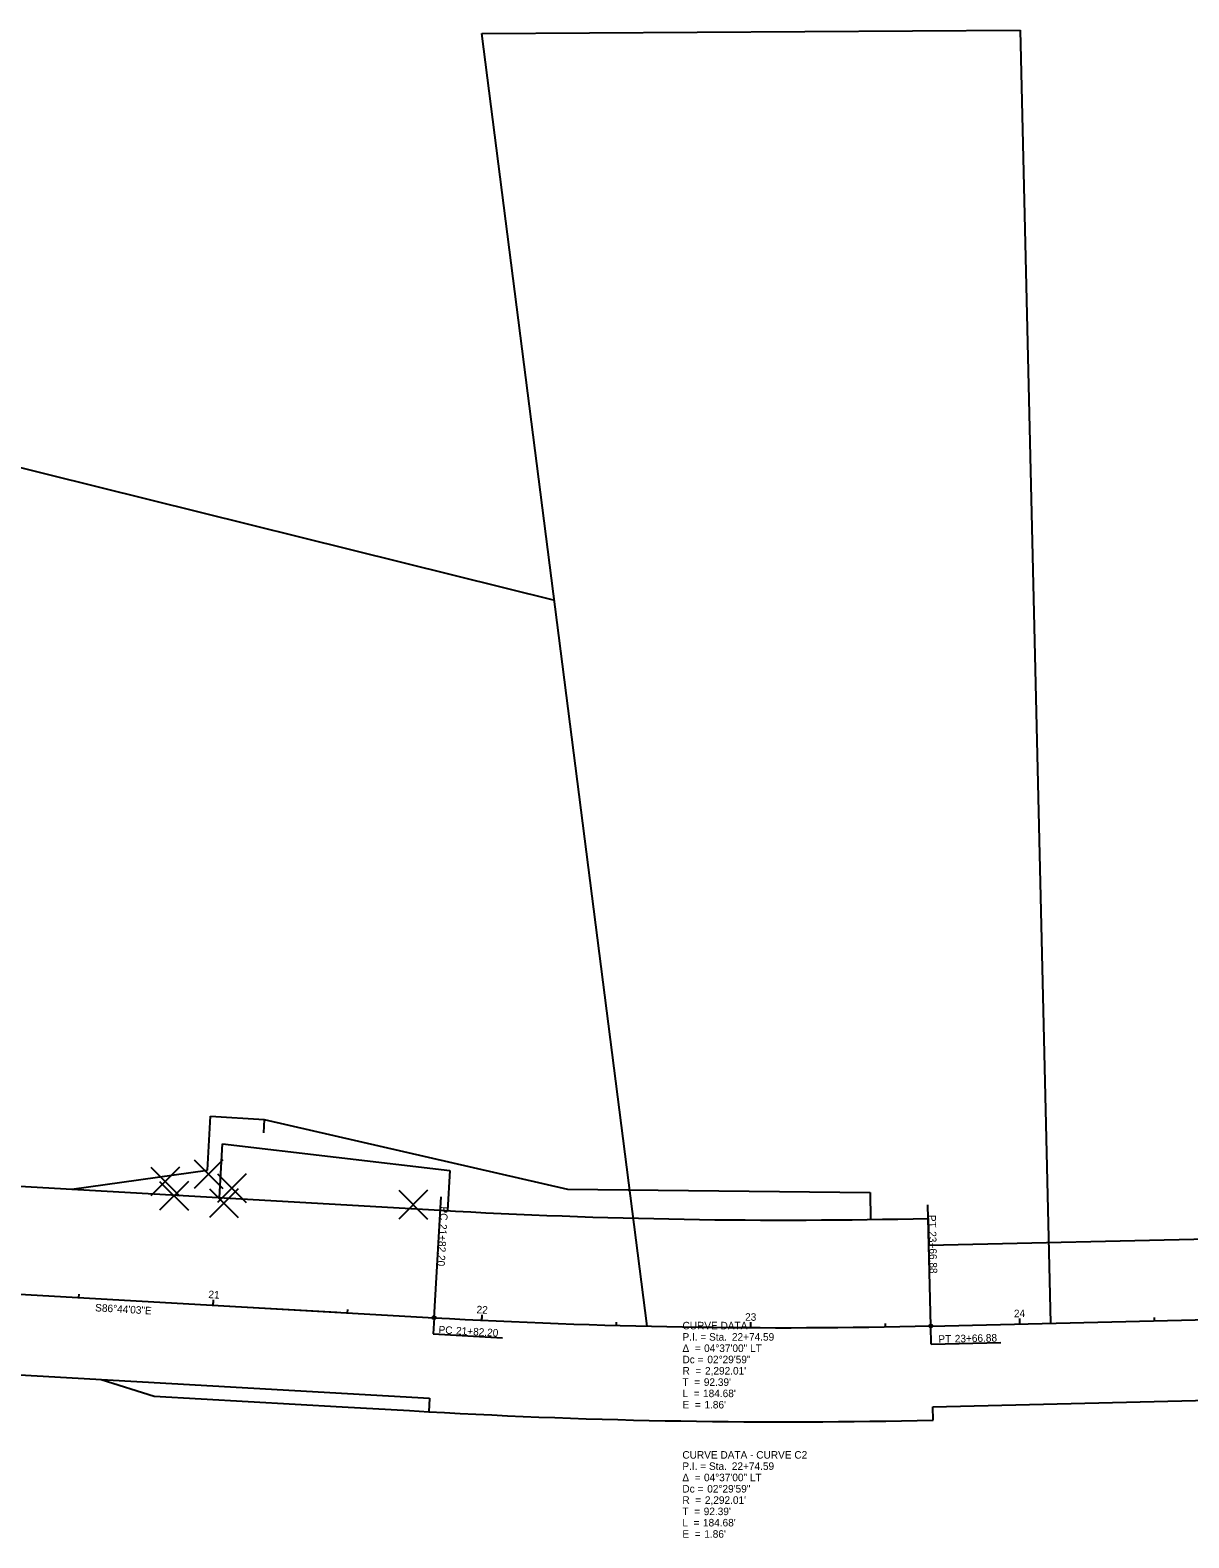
# Model space of a CAD drawing. Extents: x 2273856 to 2278684, y 652916 to 655179.
# Drawn here: x 2274537 to 2274968, y 654619 to 655179 of the extents above; entities that cross this region are included whole.
import ezdxf

# ---------------------------------------------------------------- set-up
doc = ezdxf.new("R2010")
doc.units = 0
for name, color, linetype in [('DV_X_Property_Line', 7, 'Continuous'), ('RW_P_Esmt_SH', 7, 'Continuous'), ('RW_P_Esmt_TMP', 7, 'Continuous'), ('RW_X_CL', 7, 'Continuous'), ('RW_X_CL_1000_Curve_Data', 7, 'Continuous'), ('RW_X_CL_1000_Stations', 7, 'Continuous'), ('RW_X_CL_100_Curve_Data', 7, 'Continuous'), ('RW_X_CL_100_Stations', 7, 'Continuous'), ('RW_X_CL_500_Curve_Data', 7, 'Continuous'), ('RW_X_CL_500_Stations', 7, 'Continuous'), ('RW_X_Esmt_SH', 7, 'Continuous'), ('SC_Scratch1', 7, 'Continuous'), ('VG_P_Cells', 7, 'Continuous')]:
    doc.layers.add(name, color=color, linetype=linetype)

msp = doc.modelspace()

# ---------------------------------------------------------------- linework, layer by layer
at = {"layer": 'DV_X_Property_Line'}
for p, q in [((2274705.29, 655177.83), (2274905.28, 655179.09)), ((2274766.64, 654697.37), (2274705.29, 655177.83)), ((2274905.28, 655179.09), (2274916.62, 654698.48)), ((2274486.83, 655028.17), (2274732.19, 654967.18))]:
    msp.add_line(p, q, dxfattribs=at)
at = {"layer": 'RW_P_Esmt_SH'}
for p, q in [((2274607.72, 654745.14), (2274608.86, 654765.1)), ((2274608.86, 654765.1), (2274693.37, 654755.28)), ((2274693.37, 654755.28), (2274692.53, 654740.3))]:
    msp.add_line(p, q, dxfattribs=at)
at = {"layer": 'RW_P_Esmt_TMP'}
for p, q in [((2274603.3, 654755.41), (2274604.43, 654775.37)), ((2274603.3, 654755.41), (2274604.43, 654775.37)), ((2274604.43, 654775.37), (2274624.4, 654774.23)), ((2274604.43, 654775.37), (2274624.4, 654774.23)), ((2274624.4, 654774.23), (2274624.12, 654769.24)), ((2274624.4, 654774.23), (2274737.06, 654748.26)), ((2274624.4, 654774.23), (2274737.06, 654748.26)), ((2274552.81, 654748.27), (2274603.3, 654755.41)), ((2274552.81, 654748.27), (2274603.3, 654755.41)), ((2274737.06, 654748.26), (2274849.53, 654747.02)), ((2274737.06, 654748.26), (2274849.53, 654747.02)), ((2274849.53, 654747.02), (2274849.67, 654737.02)), ((2274849.53, 654747.02), (2274849.67, 654737.02)), ((2274563.8, 654677.53), (2274583.48, 654671.4)), ((2274583.48, 654671.4), (2274653.36, 654667.41)), ((2274653.36, 654667.41), (2274678.32, 654665.99)), ((2274678.32, 654665.99), (2274685.51, 654665.58))]:
    msp.add_line(p, q, dxfattribs=at)
at = {"layer": 'RW_X_CL'}
for p, q in [((2274458.12, 654713.61), (2274687.5, 654700.52)), ((2274872.11, 654697.43), (2275371.97, 654709.22))]:
    msp.add_line(p, q, dxfattribs=at)
msp.add_arc((2274818.07, 656988.81), 2292.01, 266.73428, 271.35095, dxfattribs=at)
at = {"layer": 'RW_X_CL_1000_Stations'}
for p, q in [((2274687.5, 654700.52), (2274690.07, 654745.45)), ((2274872.11, 654697.43), (2274871.05, 654742.42))]:
    msp.add_line(p, q, dxfattribs=at)
for centre in [(2274687.5, 654700.52), (2274872.11, 654697.43)]:
    msp.add_circle(centre, 0.6, dxfattribs=at)
at = {"layer": 'RW_X_CL_100_Stations'}
for p, q in [((2274555.52, 654708.05), (2274555.59, 654709.25)), ((2274605.44, 654705.2), (2274605.55, 654707.2)), ((2274655.36, 654702.35), (2274655.43, 654703.55)), ((2274705.28, 654699.57), (2274705.38, 654701.57)), ((2274687.5, 654700.52), (2274687.16, 654694.53)), ((2274755.24, 654697.66), (2274755.28, 654698.86)), ((2274805.23, 654696.83), (2274805.25, 654698.83)), ((2274855.23, 654697.1), (2274855.21, 654698.3)), ((2274872.27, 654690.69), (2274872.11, 654697.43)), ((2274905.22, 654698.22), (2274905.17, 654700.21)), ((2274955.21, 654699.39), (2274955.18, 654700.59)), ((2274687.16, 654694.53), (2274712.88, 654693.07)), ((2274872.27, 654690.69), (2274898.15, 654691.3))]:
    msp.add_line(p, q, dxfattribs=at)
for centre in [(2274687.5, 654700.52), (2274872.11, 654697.43)]:
    msp.add_circle(centre, 0.6, dxfattribs=at)
at = {"layer": 'RW_X_CL_500_Stations'}
for p, q in [((2274687.5, 654700.52), (2274690.07, 654745.45)), ((2274872.11, 654697.43), (2274871.05, 654742.42)), ((2274605.44, 654705.2), (2274605.51, 654706.4)), ((2274705.28, 654699.57), (2274705.34, 654700.77)), ((2274805.23, 654696.83), (2274805.24, 654698.03)), ((2274905.22, 654698.22), (2274905.19, 654699.42))]:
    msp.add_line(p, q, dxfattribs=at)
for centre in [(2274687.5, 654700.52), (2274872.11, 654697.43)]:
    msp.add_circle(centre, 0.6, dxfattribs=at)
at = {"layer": 'RW_X_Esmt_SH'}
for p, q in [((2274460.4, 654753.54), (2274689.78, 654740.45)), ((2274871.17, 654737.42), (2274871.4, 654727.43)), ((2274871.4, 654727.43), (2275371.26, 654739.21)), ((2274456.41, 654683.66), (2274685.8, 654670.57)), ((2274872.82, 654667.44), (2275372.68, 654679.23)), ((2274685.8, 654670.57), (2274685.51, 654665.58)), ((2274872.94, 654662.44), (2274872.82, 654667.44))]:
    msp.add_line(p, q, dxfattribs=at)
for radius in [2252.01, 2327.01]:
    msp.add_arc((2274818.07, 656988.81), radius, 266.73428, 271.35095, dxfattribs=at)
at = {"layer": 'SC_Scratch1'}
msp.add_line((2274611.43, 654704.86), (2274651.36, 654702.58), dxfattribs=at)
at = {"layer": 'VG_P_Cells'}
for p, q in [((2274598.34, 654759.23), (2274609.03, 654748.54)), ((2274609.03, 654759.23), (2274598.34, 654748.54)), ((2274582.24, 654756.5), (2274592.93, 654745.81)), ((2274592.93, 654756.5), (2274582.24, 654745.81)), ((2274603.68, 654753.88), (2274603.68, 654753.88)), ((2274606.95, 654753.99), (2274617.64, 654743.3)), ((2274617.64, 654753.99), (2274606.95, 654743.3)), ((2274585.5, 654751.15), (2274596.19, 654740.46)), ((2274596.19, 654751.15), (2274585.5, 654740.46)), ((2274587.58, 654751.16), (2274587.58, 654751.16)), ((2274603.99, 654748.46), (2274614.68, 654737.77)), ((2274614.68, 654748.46), (2274603.99, 654737.77)), ((2274612.3, 654748.64), (2274612.3, 654748.64)), ((2274674.38, 654747.89), (2274685.07, 654737.2)), ((2274685.07, 654747.89), (2274674.38, 654737.2)), ((2274590.84, 654745.81), (2274590.84, 654745.81)), ((2274609.34, 654743.11), (2274609.34, 654743.11)), ((2274679.73, 654742.55), (2274679.73, 654742.55))]:
    msp.add_line(p, q, dxfattribs=at)

# ---------------------------------------------------------------- texts
at = {"layer": 'RW_X_CL_1000_Curve_Data'}
msp.add_text('S86°44\'03"E', height=2.8, rotation=356.7343, dxfattribs=at).set_placement((2274561.48, 654702.9))
for s, p in [('CURVE DATA', (2274779.81, 654696.18)), ('Δ  = ', (2274779.81, 654687.78)), ('P.I. = Sta. ', (2274779.81, 654691.98)), ('04°37\'00" LT', (2274787.83, 654687.78)), ('22+74.59', (2274798.18, 654691.98)), ('Dc = ', (2274779.81, 654683.58)), ('02°29\'59"', (2274789.05, 654683.58)), ('R  = ', (2274779.81, 654679.38)), ("2,292.01'", (2274788.18, 654679.38)), ('T  = ', (2274779.81, 654675.18)), ('L  = ', (2274779.81, 654670.98)), ("184.68'", (2274787.45, 654670.98)), ("92.39'", (2274787.74, 654675.18)), ('E  = ', (2274779.81, 654666.78)), ("1.86'", (2274787.96, 654666.78))]:
    msp.add_text(s, height=2.8, dxfattribs=at).set_placement(p)
at = {"layer": 'RW_X_CL_1000_Stations'}
for s, rotation, p in [('PC', 266.7343, (2274689.92, 654741.94)), ('21+82.20', 266.7343, (2274689.54, 654735.43)), ('PT', 271.351, (2274871.18, 654738.69)), ('23+66.88', 271.351, (2274871.33, 654732.61))]:
    msp.add_text(s, height=2.8, rotation=rotation, dxfattribs=at).set_placement(p)
at = {"layer": 'RW_X_CL_100_Curve_Data'}
msp.add_text('S86°44\'03"E', height=2.8, rotation=356.7343, dxfattribs=at).set_placement((2274561.48, 654702.9))
msp.add_text('S86°44\'03"E', height=2.8, rotation=356.7343, dxfattribs=at).set_placement((2274561.48, 654702.9))
for s, p in [('CURVE DATA - CURVE C2', (2274779.77, 654648.13)), ('P.I. = Sta. ', (2274779.77, 654643.93)), ('22+74.59', (2274798.14, 654643.93)), ('Δ  = ', (2274779.77, 654639.73)), ('04°37\'00" LT', (2274787.79, 654639.73)), ('Dc = ', (2274779.77, 654635.53)), ('02°29\'59"', (2274789.01, 654635.53)), ('T  = ', (2274779.77, 654627.13)), ('R  = ', (2274779.77, 654631.33)), ("92.39'", (2274787.7, 654627.13)), ("2,292.01'", (2274788.14, 654631.33)), ('L  = ', (2274779.77, 654622.93)), ("184.68'", (2274787.42, 654622.93)), ('E  = ', (2274779.77, 654618.73)), ("1.86'", (2274787.92, 654618.73))]:
    msp.add_text(s, height=2.8, dxfattribs=at).set_placement(p)
at = {"layer": 'RW_X_CL_100_Stations'}
for s, rotation, p in [('21', 356.7343, (2274603.56, 654707.81)), ('22', 357.1793, (2274703.22, 654702.18)), ('23', 359.6791, (2274803.07, 654699.39)), ('24', 1.351, (2274903.01, 654700.66)), ('PC', 356.7343, (2274689.09, 654694.71)), ('21+82.20', 356.7343, (2274695.6, 654694.34)), ('PT', 1.351, (2274874.95, 654691.17)), ('23+66.88', 1.351, (2274881.03, 654691.31))]:
    msp.add_text(s, height=2.8, rotation=rotation, dxfattribs=at).set_placement(p)
at = {"layer": 'RW_X_CL_500_Curve_Data'}
for s, p in [('CURVE DATA', (2274779.81, 654696.18)), ('Δ  = ', (2274779.81, 654687.78)), ('P.I. = Sta. ', (2274779.81, 654691.98)), ('04°37\'00" LT', (2274787.83, 654687.78)), ('22+74.59', (2274798.18, 654691.98)), ('Dc = ', (2274779.81, 654683.58)), ('02°29\'59"', (2274789.05, 654683.58)), ('R  = ', (2274779.81, 654679.38)), ("2,292.01'", (2274788.18, 654679.38)), ('T  = ', (2274779.81, 654675.18)), ('L  = ', (2274779.81, 654670.98)), ("184.68'", (2274787.45, 654670.98)), ("92.39'", (2274787.74, 654675.18)), ('E  = ', (2274779.81, 654666.78)), ("1.86'", (2274787.96, 654666.78))]:
    msp.add_text(s, height=2.8, dxfattribs=at).set_placement(p)
at = {"layer": 'RW_X_CL_500_Stations'}
for s, rotation, p in [('PC', 266.7343, (2274689.92, 654741.94)), ('21+82.20', 266.7343, (2274689.54, 654735.43)), ('PT', 271.351, (2274871.18, 654738.69)), ('23+66.88', 271.351, (2274871.33, 654732.61))]:
    msp.add_text(s, height=2.8, rotation=rotation, dxfattribs=at).set_placement(p)

doc.saveas('drawing.dxf')
